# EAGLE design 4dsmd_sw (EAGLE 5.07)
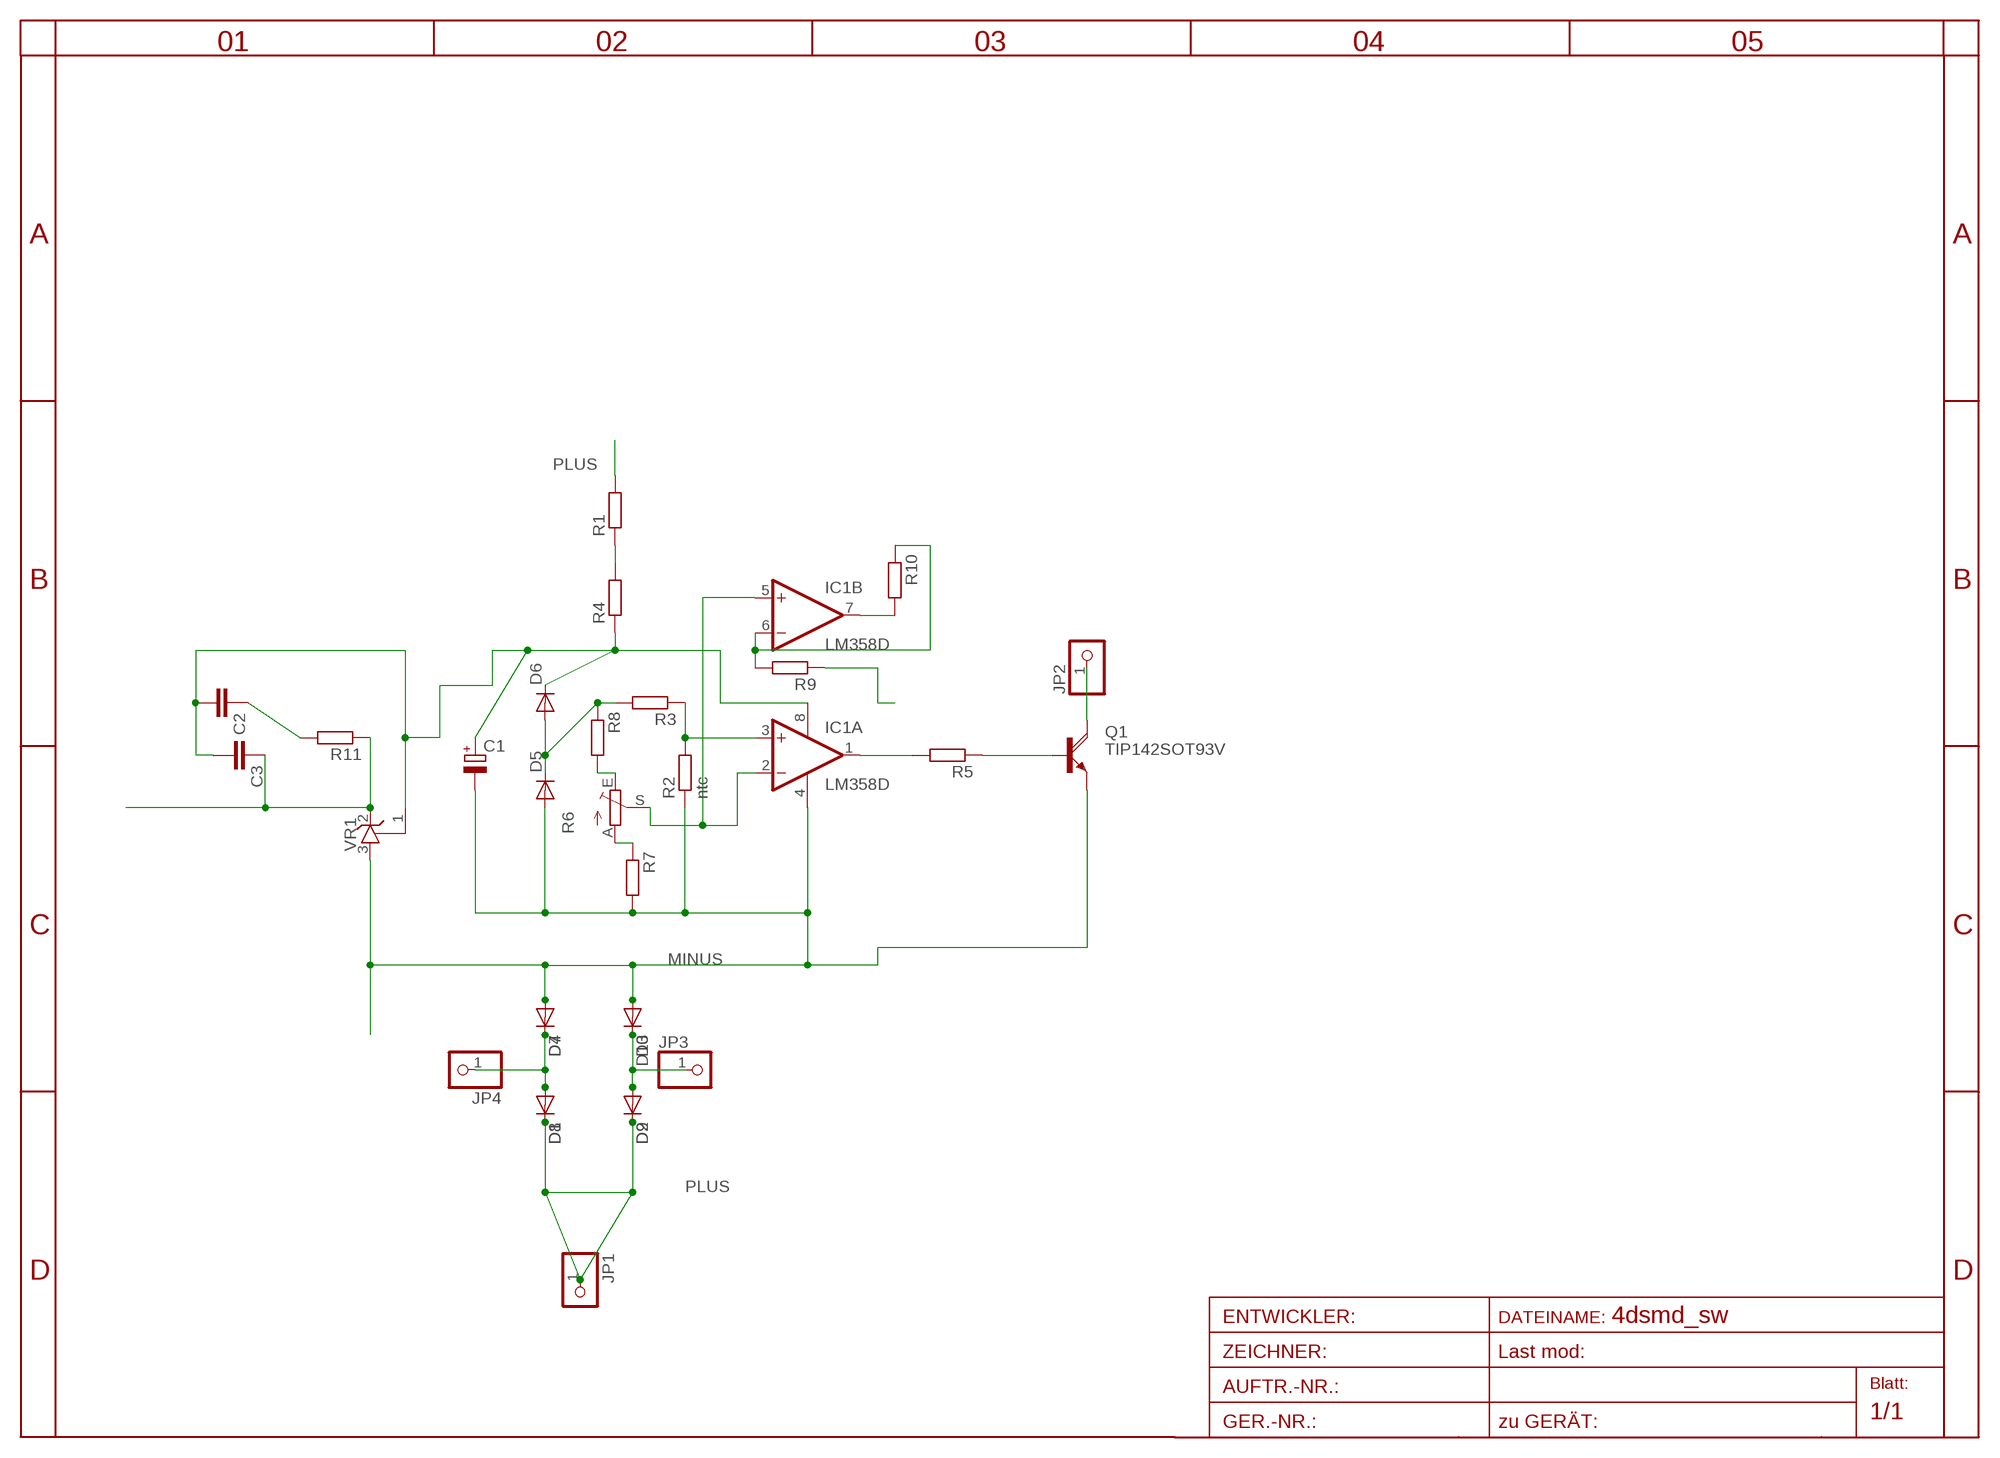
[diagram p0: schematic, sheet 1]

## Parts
C1  CPOL-EUSANYO_SMD_C6  [SANYO-OSCON_SMD_C6]
C2  C-EUC0805  [C0805]
C3  C-EUC0805  [C0805]
D1  DIODE-SMC  [SMC]
D2  DIODE-SMC  [SMC]
D3  DIODE-SMC  [SMC]
D4  DIODE-SMC  [SMC]
D5  DIODE-MINIMELF  [MINIMELF]
D6  DIODE-MINIMELF  [MINIMELF]
D7  DIODE-SMC  [SMC]
D8  DIODE-SMC  [SMC]
D9  DIODE-SMC  [SMC]
D10  DIODE-SMC  [SMC]
IC1  LM358D  [SO08]
JP1  PINHD-1X12MM2  [1X2MM2]
JP2  PINHD-1X12MM2  [1X2MM2]
JP3  PINHD-1X12MM2  [1X2MM2]
JP4  PINHD-1X12MM2  [1X2MM2]
Q1  TIP142SOT93V  [SOT93V]
R1  R-EU_R1206  [R1206]
R2  ntc  R-EU_0204/5  [0204/5]
R3  R-EU_R1206  [R1206]
R4  R-EU_R1206  [R1206]
R5  R-EU_R1206  [R1206]
R6  TRIM_EU-RAND160  [RANDL]
R7  R-EU_R1206  [R1206]
R8  R-EU_R1206  [R1206]
R9  R-EU_R1206  [R1206]
R10  R-EU_R1206  [R1206]
R11  R-EU_R0805  [R0805]
VR1  TL431CLPSOT23  [SOT23]

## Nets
2V5: C3.1 D5.C D6.A R3.2 R8.1 R11.1 VR1.2(C)
AC1: D1.A D4.C D7.C D8.A JP4.1
AC2: D2.A D3.C D9.A D10.C JP3.1
MINUS: C1.- D3.A D4.A D5.A D7.A D10.A IC1.4(P:V-) IC1.6(B:-IN) Q1.E R2.1 R7.2 R9.1 R9.2 R10.1 VR1.3(A)
N$2: IC1.2(A:-IN) IC1.5(B:+IN) R6.S
N$3: IC1.1(A:OUT) R5.2
N$5: IC1.3(A:+IN) R2.2 R3.1
N$6: Q1.B R5.1
N$7: R6.A R7.1
N$8: JP2.1 Q1.C
N$9: R6.E R8.2
N$10: R1.1 R4.2
N$11: IC1.7(B:OUT) R10.2
N$13: C2.1 R11.2
PLUS: D1.C D2.C D8.C D9.C JP1.1 R1.2
S: C1.+ C2.2 C3.2 D6.C IC1.8(P:V+) R4.1 VR1.1(R)

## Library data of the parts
C1 = rcl:CPOL-EU: POLARIZED CAPACITOR, European symbol
C2 C3 = rcl:C-EU: CAPACITOR, European symbol
D1-D10 = diode:DIODE-: DIODE
IC1 = linear:LM358: OP AMP also LM158; LM258; LM2904 Source: http://cache.national.com/ds/LM/LM158.pdf
JP1-JP4 = pinhead:PINHD-1X1: PIN HEADER
Q1 = transistor-power:TIP142: NPN DARLINGTON TRANSISTOR
R1-R5 R7-R11 = rcl:R-EU_: RESISTOR, European symbol
R6 = pot:TRIM_EU-: POTENTIOMETER
VR1 = v-reg:TL431CLP: VOLTAGE REGULATOR

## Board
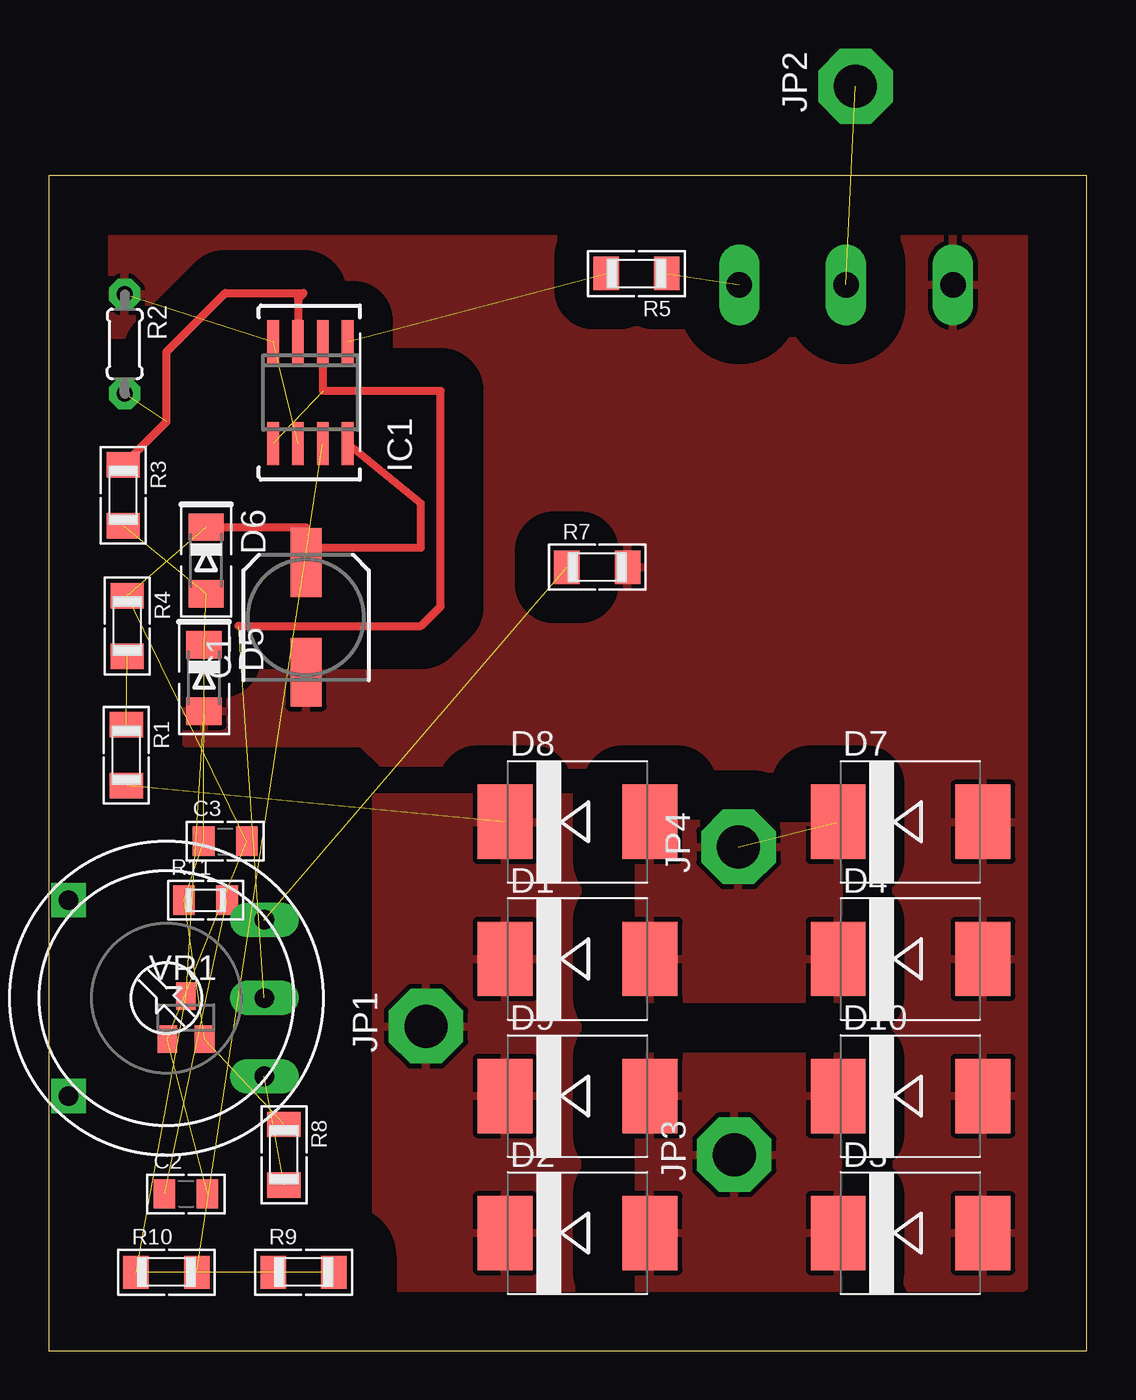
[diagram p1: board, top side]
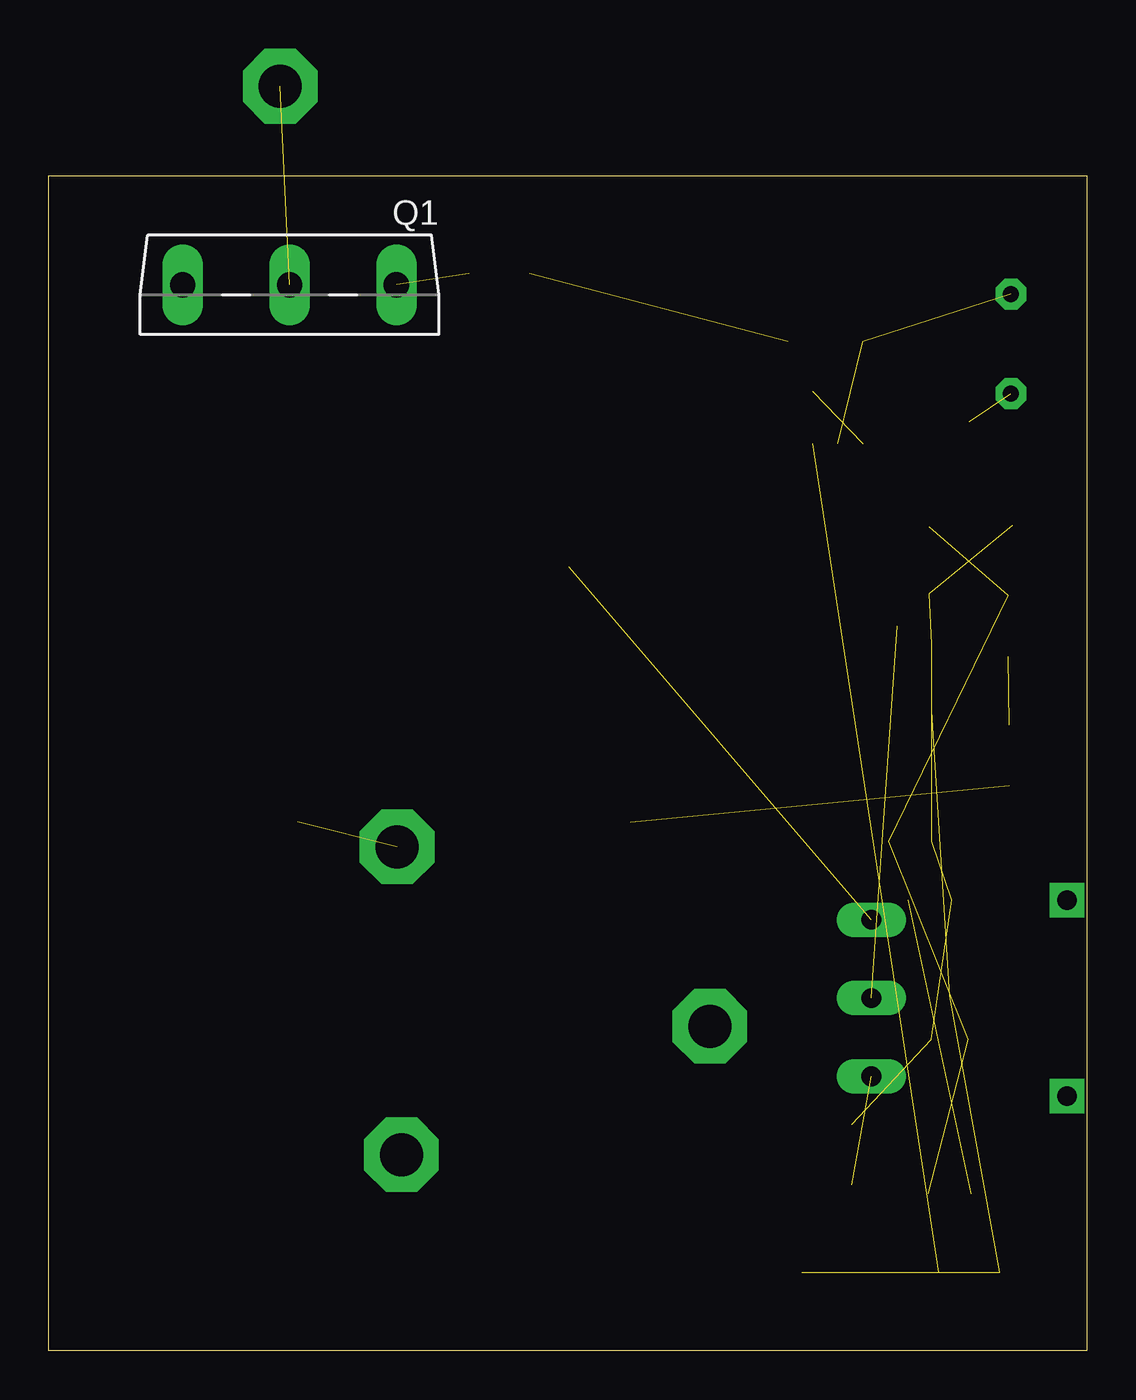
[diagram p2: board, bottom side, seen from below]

Size 53 x 60 mm. Coordinates in mm from the lower left corner, seen from the top.
Outline: 0,0 53,0 53,60 0,60 0,0
Copper layers (1*16): Top 0.035mm / dielectric 1.5mm / Bottom 0.035mm
Design rules "default *": minimum track width 10mil, minimum drill 20mil, track to track 8mil, track to pad 8mil, pad to pad 8mil, via to via 8mil, smd to smd 8mil, copper to edge 3mm, drill to drill 8mil, minimum pad ring 15mil, minimum via ring 8mil, stop-mask expansion 4mil, vias tented up to drill 0mil, thermal gap 10mil

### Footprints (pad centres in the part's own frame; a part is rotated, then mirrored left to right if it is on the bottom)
SANYO-OSCON_SMD_C6 = smd 3.5 x 1.6: + 2.8,0; - -2.8,0
C0805 = smd 1.1 x 1.5: 1 -1.1,0; 2 1.1,0
SMC = smd 2.8 x 3.8: A 3.7,0; C -3.7,0
MINIMELF = smd 1.4 x 1.8: A 1.7,0; C -1.7,0
SO08 = smd 0.6 x 2.2: 1 -1.905,-2.6; 2 -0.635,-2.6; 3 0.635,-2.6; 4 1.905,-2.6; 5 1.905,2.6; 6 0.635,2.6; 7 -0.635,2.6; 8 -1.905,2.6
1X2MM2 = drill 2.2 pad 3.81 octagon: 1 0,0
SOT93V = drill 1.3 pad 1.676 long: B -5.461,-2.54; C 0,-2.54; E 5.461,-2.54
R1206 = smd 1.3 x 1.7: 1 -1.55,0; 2 1.55,0
0204/5 = drill 0.813 octagon: 1 -2.54,0; 2 2.54,0
RANDL = drill 1 long: A -4,5; E 4,5; S 0,5 | drill 1 square: P$1 -5,-5; P$2 5,-5
R0805 = smd 1.1 x 1.5: 1 -1.1,0; 2 1.1,0
SOT23 = smd 1 x 1.4: 1 -0.95,-1.1; 2 0.95,-1.1; 3 0,1.1

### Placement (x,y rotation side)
C1  13.13,37.44 90 top
C2  7,8 0 top
C3  9,26 0 top
D1  27,20 0 top
D2  27,6 0 top
D3  44,6 0 top
D4  44,20 0 top
D5  7.92,34.35 270 top
D6  8.03,40.35 270 top
D7  44,27 0 top
D8  27,27 0 top
D9  27,13 0 top
D10  44,13 0 top
IC1  13.35,48.92 180 top
JP1  19.25,16.56 90 top
JP2  not placed on the board
JP3  35,10 90 top
JP4  35.22,25.72 90 top
Q1  40.71,51.88 180 bottom
R1  3.95,30.4 270 top
R2  3.87,51.4 270 top
R3  3.79,43.67 270 top
R4  4,37 270 top
R5  30,55 180 top
R6  6,18 270 top
R7  28,40 0 top
R8  12,10 270 top
R9  13,4 0 top
R10  6,4 0 top
R11  8,23 0 top
VR1  7,17 0 top

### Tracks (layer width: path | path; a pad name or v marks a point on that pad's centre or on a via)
2V5  (6 unrouted)
AC1  (1 unrouted)
  pour Top (isolate 2.54, rank 3): 41.57,17.1 30.14,17.1 30.14,29.53 41.57,29.53
AC2
  pour Top (isolate 2.54, rank 2): 30.14,2.86 30.14,15.02 40.3,15.02 40.3,2.86
MINUS  (6 unrouted)
  pour Top (isolate 2): 44.11,2.86 42.84,5.4 42.84,29.53 42,29.53 22,30 17,30 16,31 7,31 7,33 3,48 3,59 15,59 33,57.53 50.73,58.53 51.73,4.4 49.19,2.86
N$2  (2 unrouted)
  Top 0.406: IC1.2 14,51.52 14,49 20,49 20,38 19,37 9.68,37
N$3  (1 unrouted)
N$5  (1 unrouted)
  Top 0.406: IC1.3 12.71,53.72 13,54 9,54 6,51 6,47.43 R3.1
N$6  (1 unrouted)
N$7  (1 unrouted)
N$8  (1 unrouted)
N$9  (1 unrouted)
N$10  (1 unrouted)
N$11  (1 unrouted)
N$13  (1 unrouted)
PLUS  (1 unrouted)
  pour Top (isolate 2.54): 16.71,2.86 16.71,28.26 27.6,28.26 27.6,2.86
S  (4 unrouted)
  Top 0.406: IC1.8 19,43.26 19,41 13.13,41 C1.+ 13.13,42.05 D6.C 8.03,42.12 | R4.1 3.79,38.55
